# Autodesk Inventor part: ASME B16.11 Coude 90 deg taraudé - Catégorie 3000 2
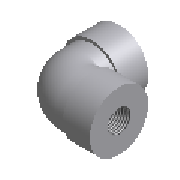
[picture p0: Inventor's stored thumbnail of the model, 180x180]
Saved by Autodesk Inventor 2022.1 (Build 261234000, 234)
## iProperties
Created: 2021-02
Part Number: ASME B16.11 Coude 90 deg taraudé - Catégorie 3000 2
Material: Acier
Description: Coude 90° taraudé - Forgé - Catégorie 3000
Document SubType Name: Modeling
Standard: ASME B16.11
Designer: Fabian
Standard Revision: 2011
Standards Organization: ANSI
Language: fr-FR
Size Designation: 2
Categories: <MemberInstance><Categories><Category DisplayName="Tubes et tuyaux" InternalName="4347fa0f-2144-441d-94cd-e3e15c92b736" Mnemonic="TUBEANDPIPE"><CategoryParamete
Density: 1 g/cm^3
Appearance: Plaque
IsCustomPart: 0
NAME: PIPING: ASME B16.11 90 Deg Elbow Threaded - Class 3000
DATA: <meta><inlinegroups number="0" deflen="0"></inlinegroups><connections number="2"></connections><angles><a>1.57079632679489</a></angles></meta>
Author: Fabian
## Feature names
1. Sweep1
2. Revolve1
3. Revolve2
4. Revolve3
5. Revolve4
6. Sweep2
## Parameters: MD = 56.55818 mm, A = 63.5 mm, L2 = 19.2151 mm, G = 7.1374 mm, d0 = 56.55818 mm, d1 = 84.074 mm, d2 = 0.3124 mm, d3 = 0.3124 mm, d4 = 56.55818 mm, d5 = 84.074 mm, H = 84.074 mm, d6 = 19.2151 mm, d7 = 61.3918 mm, d8 = 19.2151 mm, d9 = 61.3918 mm, d10 = 0, d11 = 19.05 mm, d12 = 19.05 mm, d13 = 37.8333 mm, d14 = 0, d101 = 90 deg, d102 = 90 deg, d105 = 25.4 mm, d106 = 0, d107 = 25.4 mm, d108 = 0, d15 = 63.5 mm, d16 = 31.75 mm, d17 = 63.5 mm, d18 = 31.75 mm, d19 = 75.6666 mm, d20 = 75.6666 mm, d21 = 19.05 mm, d116 = 90 deg, d117 = 90 deg, d22 = 30.69597 mm, d23 = 0, d122 = 0, d123 = 0
